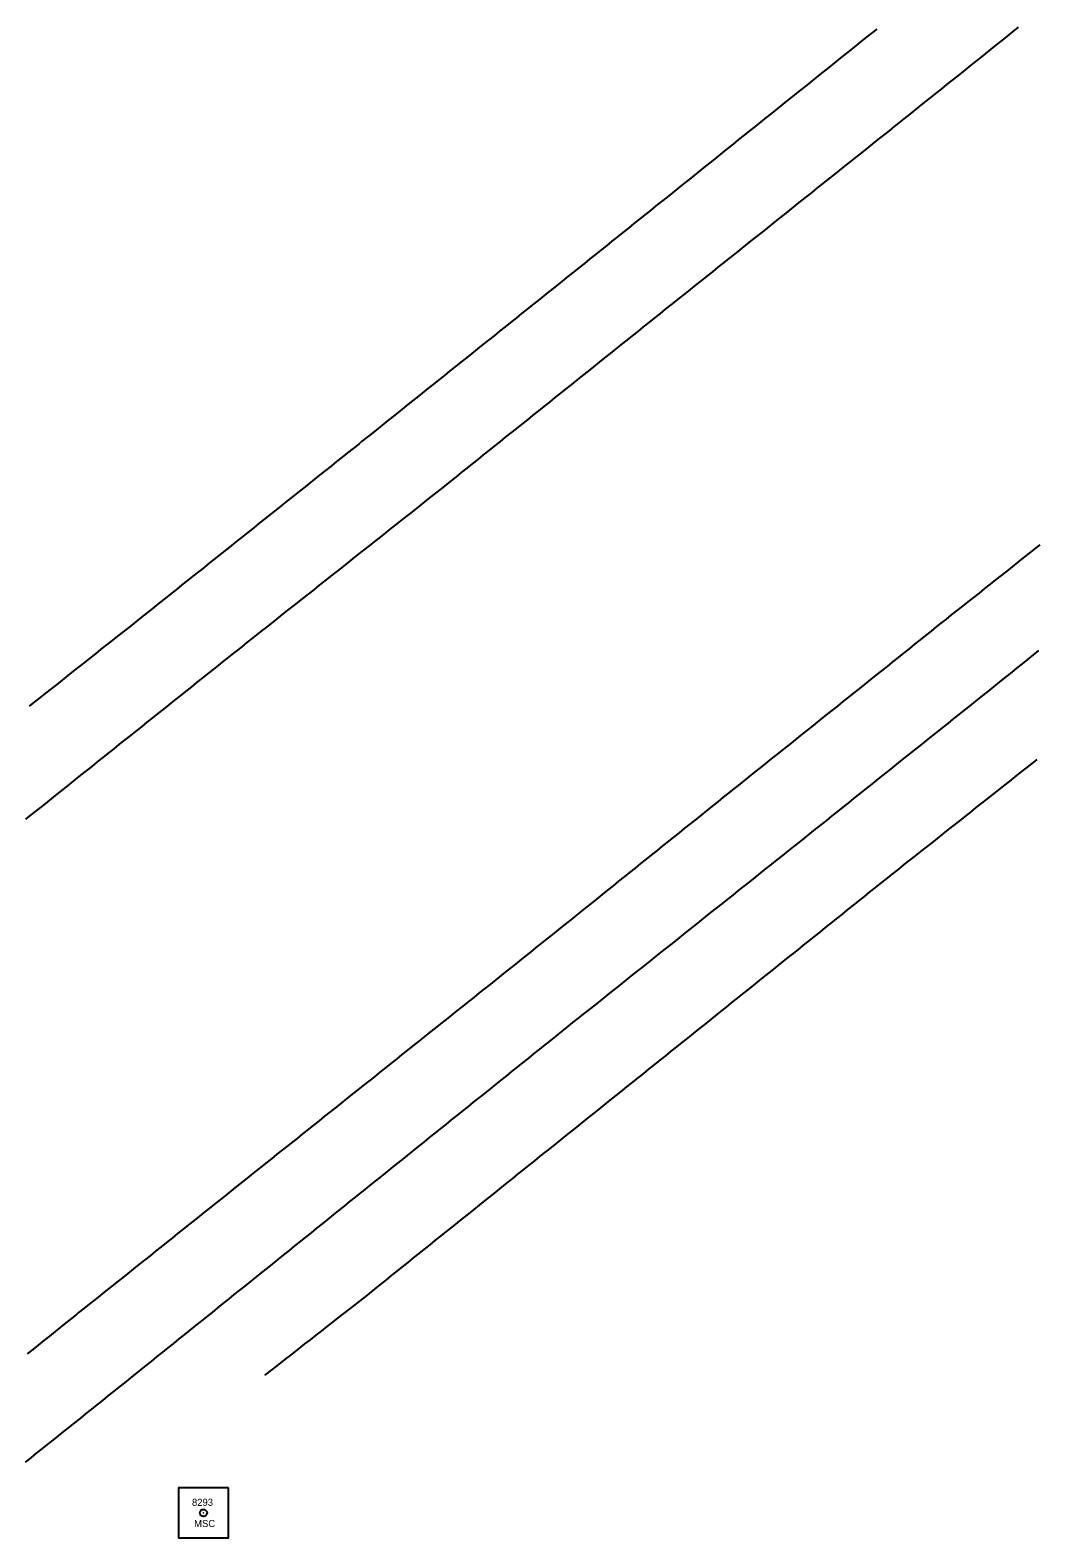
# Model space of a CAD drawing. Extents: x 205929 to 2357175, y -1785700 to 846739.
# Drawn here: x 2022372.4 to 2022514.8, y 806133.9 to 806347.3 of the extents above; entities that cross this region are included whole.
import ezdxf

# ---------------------------------------------------------------- set-up
doc = ezdxf.new("R2010")
doc.units = 0
for name, color, linetype in [('RD_HC_Survey', 7, 'Continuous'), ('RD_HC_txCode', 7, 'Continuous'), ('RD_Sketch1', 7, 'Continuous'), ('RD_SMD_Locator', 7, 'Continuous')]:
    doc.layers.add(name, color=color, linetype=linetype)

msp = doc.modelspace()

# ---------------------------------------------------------------- linework, layer by layer
at = {"layer": 'RD_HC_Survey'}
msp.add_lwpolyline([(2022400.46, 806140.98), (2022393.39, 806140.98), (2022393.39, 806133.91), (2022400.46, 806133.91)], close=True, dxfattribs=at)
msp.add_circle((2022396.93, 806137.44), 0.5, dxfattribs=at)
at = {"layer": 'RD_Sketch1'}
for points in [[(2022512.28, 806347.76), (2022511.5, 806347.14), (2022510.72, 806346.51), (2022509.94, 806345.89), (2022509.16, 806345.26), (2022508.38, 806344.64), (2022507.6, 806344.01), (2022506.82, 806343.39), (2022506.04, 806342.76), (2022505.26, 806342.14), (2022504.48, 806341.51), (2022503.7, 806340.89), (2022502.91, 806340.26), (2022502.13, 806339.64), (2022501.35, 806339.01), (2022500.57, 806338.39), (2022499.79, 806337.76), (2022499.01, 806337.14), (2022498.23, 806336.51), (2022497.45, 806335.89), (2022496.67, 806335.26), (2022495.89, 806334.64), (2022495.54, 806334.36), (2022494.76, 806333.73), (2022493.98, 806333.11), (2022493.2, 806332.49), (2022492.41, 806331.86), (2022491.63, 806331.24), (2022490.85, 806330.61), (2022490.07, 806329.99), (2022489.29, 806329.37), (2022488.51, 806328.74), (2022487.73, 806328.12), (2022486.94, 806327.49), (2022486.16, 806326.87), (2022486.16, 806326.87), (2022485.38, 806326.25), (2022484.6, 806325.62), (2022483.82, 806325), (2022483.04, 806324.37), (2022482.26, 806323.75), (2022481.47, 806323.13), (2022480.69, 806322.5), (2022479.91, 806321.88), (2022479.13, 806321.26), (2022478.35, 806320.63), (2022477.57, 806320.01), (2022476.79, 806319.38), (2022476, 806318.76), (2022475.22, 806318.14), (2022474.44, 806317.51), (2022473.66, 806316.89), (2022472.88, 806316.26), (2022472.1, 806315.64), (2022471.32, 806315.02), (2022470.53, 806314.39), (2022469.75, 806313.77), (2022468.97, 806313.14), (2022468.19, 806312.52), (2022467.41, 806311.9), (2022466.63, 806311.27), (2022465.85, 806310.65), (2022465.06, 806310.03), (2022464.28, 806309.4), (2022463.5, 806308.78), (2022463.08, 806308.44), (2022462.3, 806307.82), (2022461.52, 806307.19), (2022460.74, 806306.57), (2022459.96, 806305.94), (2022459.18, 806305.32), (2022458.4, 806304.69), (2022457.62, 806304.07), (2022456.84, 806303.44), (2022456.06, 806302.82), (2022455.28, 806302.19), (2022454.5, 806301.57), (2022453.72, 806300.94), (2022452.93, 806300.32), (2022452.15, 806299.69), (2022451.37, 806299.07), (2022450.59, 806298.44), (2022449.81, 806297.82), (2022449.03, 806297.19), (2022448.25, 806296.57), (2022447.47, 806295.94), (2022446.69, 806295.32), (2022445.91, 806294.69), (2022445.13, 806294.07), (2022444.35, 806293.44), (2022443.57, 806292.82), (2022442.79, 806292.19), (2022442.01, 806291.57), (2022441.22, 806290.95), (2022440.44, 806290.32), (2022439.66, 806289.7), (2022438.88, 806289.07), (2022438.1, 806288.45), (2022437.32, 806287.82), (2022436.54, 806287.2), (2022436.54, 806287.2), (2022435.76, 806286.57), (2022434.98, 806285.95), (2022434.2, 806285.32), (2022433.42, 806284.7), (2022432.64, 806284.07), (2022431.86, 806283.45), (2022431.34, 806283.03), (2022430.56, 806282.41), (2022429.77, 806281.79), (2022428.99, 806281.17), (2022428.21, 806280.55), (2022427.42, 806279.93), (2022426.64, 806279.31), (2022425.85, 806278.69), (2022425.07, 806278.07), (2022424.29, 806277.45), (2022423.5, 806276.82), (2022422.72, 806276.2), (2022421.93, 806275.58), (2022421.15, 806274.96), (2022420.37, 806274.34), (2022419.58, 806273.72), (2022418.8, 806273.1), (2022418.02, 806272.48), (2022417.23, 806271.86), (2022416.45, 806271.24), (2022415.66, 806270.62), (2022414.88, 806270), (2022414.1, 806269.37), (2022413.31, 806268.75), (2022412.53, 806268.13), (2022411.75, 806267.51), (2022410.96, 806266.89), (2022410.18, 806266.27), (2022409.39, 806265.65), (2022408.61, 806265.03), (2022407.83, 806264.41), (2022407.04, 806263.79), (2022406.26, 806263.17), (2022405.47, 806262.55), (2022404.69, 806261.93), (2022403.91, 806261.3), (2022403.12, 806260.68), (2022402.34, 806260.06), (2022401.56, 806259.44), (2022400.77, 806258.82), (2022400.64, 806258.72), (2022399.86, 806258.09), (2022399.08, 806257.47), (2022398.3, 806256.84), (2022397.51, 806256.22), (2022396.73, 806255.6), (2022395.95, 806254.97), (2022395.17, 806254.35), (2022394.39, 806253.72), (2022393.61, 806253.1), (2022392.83, 806252.48), (2022392.04, 806251.85), (2022391.26, 806251.23), (2022390.48, 806250.6), (2022389.7, 806249.98), (2022388.92, 806249.36), (2022388.14, 806248.73), (2022387.36, 806248.11), (2022387.36, 806248.11), (2022386.58, 806247.48), (2022385.79, 806246.86), (2022385.01, 806246.24), (2022384.23, 806245.61), (2022383.45, 806244.99), (2022382.67, 806244.36), (2022381.89, 806243.74), (2022381.11, 806243.12), (2022380.32, 806242.49), (2022379.54, 806241.87), (2022378.76, 806241.24), (2022377.98, 806240.62), (2022377.2, 806240), (2022376.42, 806239.37), (2022375.64, 806238.75), (2022374.85, 806238.12), (2022374.07, 806237.5), (2022373.29, 806236.88), (2022372.51, 806236.25), (2022371.73, 806235.63)], [(2022492.24, 806347.5), (2022491.45, 806346.87), (2022490.67, 806346.25), (2022489.89, 806345.62), (2022489.11, 806345), (2022488.33, 806344.37), (2022487.55, 806343.75), (2022486.77, 806343.12), (2022485.99, 806342.5), (2022485.21, 806341.87), (2022484.43, 806341.24), (2022483.65, 806340.62), (2022482.87, 806339.99), (2022482.09, 806339.37), (2022481.31, 806338.74), (2022480.53, 806338.12), (2022479.71, 806337.47), (2022478.93, 806336.84), (2022478.15, 806336.21), (2022477.37, 806335.59), (2022476.59, 806334.96), (2022475.81, 806334.34), (2022475.03, 806333.71), (2022474.25, 806333.09), (2022473.47, 806332.46), (2022472.69, 806331.84), (2022471.91, 806331.21), (2022471.13, 806330.58), (2022470.35, 806329.96), (2022469.57, 806329.33), (2022468.79, 806328.71), (2022468.01, 806328.08), (2022467.23, 806327.46), (2022467.23, 806327.46), (2022466.45, 806326.83), (2022465.67, 806326.21), (2022464.89, 806325.58), (2022464.11, 806324.95), (2022463.33, 806324.33), (2022462.55, 806323.7), (2022461.77, 806323.08), (2022460.99, 806322.45), (2022460.21, 806321.83), (2022459.43, 806321.2), (2022458.65, 806320.58), (2022457.87, 806319.95), (2022457.09, 806319.33), (2022456.31, 806318.7), (2022455.53, 806318.07), (2022454.75, 806317.45), (2022453.97, 806316.82), (2022453.19, 806316.2), (2022452.41, 806315.57), (2022451.63, 806314.95), (2022450.85, 806314.32), (2022450.07, 806313.7), (2022449.29, 806313.07), (2022449, 806312.83), (2022448.22, 806312.21), (2022447.43, 806311.58), (2022446.65, 806310.96), (2022445.87, 806310.33), (2022445.09, 806309.71), (2022444.31, 806309.09), (2022443.53, 806308.46), (2022442.75, 806307.84), (2022441.97, 806307.21), (2022441.19, 806306.59), (2022440.41, 806305.96), (2022439.63, 806305.34), (2022438.85, 806304.71), (2022438.06, 806304.09), (2022437.28, 806303.46), (2022436.5, 806302.84), (2022435.72, 806302.21), (2022434.94, 806301.59), (2022434.16, 806300.96), (2022433.38, 806300.34), (2022432.6, 806299.71), (2022431.82, 806299.09), (2022431.04, 806298.46), (2022430.26, 806297.84), (2022429.48, 806297.22), (2022428.69, 806296.59), (2022427.91, 806295.97), (2022427.13, 806295.34), (2022426.35, 806294.72), (2022425.57, 806294.09), (2022424.79, 806293.47), (2022424.01, 806292.84), (2022423.23, 806292.22), (2022422.45, 806291.59), (2022421.67, 806290.97), (2022420.89, 806290.34), (2022420.11, 806289.72), (2022419.32, 806289.09), (2022418.9, 806288.75), (2022418.11, 806288.13), (2022418.11, 806288.13), (2022417.33, 806287.5), (2022416.55, 806286.88), (2022415.77, 806286.26), (2022414.99, 806285.63), (2022414.21, 806285.01), (2022413.42, 806284.39), (2022412.64, 806283.76), (2022411.86, 806283.14), (2022411.08, 806282.52), (2022410.3, 806281.89), (2022409.52, 806281.27), (2022408.73, 806280.65), (2022407.95, 806280.02), (2022407.17, 806279.4), (2022406.39, 806278.77), (2022405.61, 806278.15), (2022404.83, 806277.53), (2022404.04, 806276.9), (2022403.26, 806276.28), (2022402.48, 806275.66), (2022401.7, 806275.03), (2022400.92, 806274.41), (2022400.13, 806273.79), (2022399.35, 806273.16), (2022398.57, 806272.54), (2022397.79, 806271.92), (2022397.01, 806271.29), (2022396.23, 806270.67), (2022395.44, 806270.05), (2022394.66, 806269.42), (2022393.88, 806268.8), (2022393.1, 806268.18), (2022392.32, 806267.55), (2022391.54, 806266.93), (2022390.75, 806266.3), (2022389.97, 806265.68), (2022389.19, 806265.06), (2022388.41, 806264.43), (2022387.63, 806263.81), (2022387.13, 806263.41), (2022386.34, 806262.79), (2022385.56, 806262.17), (2022384.78, 806261.55), (2022383.99, 806260.93), (2022383.21, 806260.31), (2022382.42, 806259.69), (2022381.64, 806259.07), (2022380.86, 806258.45), (2022380.07, 806257.83), (2022379.29, 806257.21), (2022378.5, 806256.59), (2022377.72, 806255.97), (2022376.94, 806255.34), (2022376.15, 806254.72), (2022375.37, 806254.1), (2022374.58, 806253.48), (2022373.8, 806252.86), (2022373.02, 806252.24), (2022372.23, 806251.62)], [(2022515.34, 806274.5), (2022514.55, 806273.87), (2022513.77, 806273.25), (2022512.99, 806272.63), (2022512.2, 806272.01), (2022511.42, 806271.39), (2022510.64, 806270.77), (2022509.85, 806270.15), (2022509.07, 806269.52), (2022508.29, 806268.9), (2022507.5, 806268.28), (2022506.72, 806267.66), (2022505.94, 806267.04), (2022505.15, 806266.42), (2022504.37, 806265.8), (2022503.59, 806265.17), (2022502.8, 806264.55), (2022502.02, 806263.93), (2022501.51, 806263.52), (2022500.72, 806262.9), (2022499.94, 806262.27), (2022499.16, 806261.65), (2022498.38, 806261.02), (2022497.6, 806260.4), (2022496.82, 806259.78), (2022496.04, 806259.15), (2022495.26, 806258.53), (2022494.48, 806257.9), (2022493.7, 806257.28), (2022492.91, 806256.65), (2022492.13, 806256.03), (2022491.35, 806255.41), (2022490.57, 806254.78), (2022489.79, 806254.16), (2022489.01, 806253.53), (2022488.23, 806252.91), (2022487.45, 806252.28), (2022486.67, 806251.66), (2022485.89, 806251.03), (2022485.1, 806250.41), (2022484.32, 806249.79), (2022483.54, 806249.16), (2022482.76, 806248.54), (2022481.98, 806247.91), (2022481.2, 806247.29), (2022480.42, 806246.66), (2022479.64, 806246.04), (2022478.86, 806245.42), (2022478.08, 806244.79), (2022477.29, 806244.17), (2022476.51, 806243.54), (2022476.51, 806243.54), (2022475.73, 806242.92), (2022474.95, 806242.29), (2022474.17, 806241.67), (2022473.39, 806241.04), (2022472.61, 806240.42), (2022472.07, 806239.99), (2022471.29, 806239.36), (2022470.51, 806238.74), (2022469.73, 806238.11), (2022468.95, 806237.49), (2022468.17, 806236.86), (2022467.39, 806236.23), (2022466.61, 806235.61), (2022465.83, 806234.98), (2022465.05, 806234.36), (2022464.27, 806233.73), (2022463.49, 806233.11), (2022462.71, 806232.48), (2022461.93, 806231.85), (2022461.15, 806231.23), (2022460.37, 806230.6), (2022459.59, 806229.98), (2022458.81, 806229.35), (2022458.03, 806228.72), (2022457.25, 806228.1), (2022456.47, 806227.47), (2022455.69, 806226.85), (2022454.91, 806226.22), (2022454.13, 806225.59), (2022453.35, 806224.97), (2022452.57, 806224.34), (2022451.8, 806223.72), (2022451.02, 806223.09), (2022450.24, 806222.47), (2022449.46, 806221.84), (2022448.68, 806221.21), (2022447.9, 806220.59), (2022447.12, 806219.96), (2022446.34, 806219.34), (2022445.56, 806218.71), (2022444.78, 806218.08), (2022444, 806217.46), (2022443.22, 806216.83), (2022442.44, 806216.21), (2022441.66, 806215.58), (2022440.88, 806214.95), (2022440.66, 806214.78), (2022439.88, 806214.16), (2022439.1, 806213.54), (2022438.32, 806212.91), (2022437.54, 806212.29), (2022436.75, 806211.66), (2022435.97, 806211.04), (2022435.19, 806210.42), (2022434.41, 806209.79), (2022433.63, 806209.17), (2022432.85, 806208.55), (2022432.06, 806207.92), (2022431.28, 806207.3), (2022430.5, 806206.68), (2022429.72, 806206.05), (2022428.94, 806205.43), (2022428.15, 806204.81), (2022427.37, 806204.18), (2022427.37, 806204.18), (2022426.59, 806203.56), (2022425.81, 806202.94), (2022425.03, 806202.31), (2022424.25, 806201.69), (2022423.46, 806201.06), (2022422.68, 806200.44), (2022421.9, 806199.82), (2022421.12, 806199.19), (2022420.34, 806198.57), (2022419.56, 806197.95), (2022418.77, 806197.32), (2022417.99, 806196.7), (2022417.21, 806196.08), (2022416.43, 806195.45), (2022415.65, 806194.83), (2022414.86, 806194.21), (2022414.08, 806193.58), (2022413.3, 806192.96), (2022412.52, 806192.33), (2022411.74, 806191.71), (2022410.96, 806191.09), (2022410.17, 806190.46), (2022409.39, 806189.84), (2022408.9, 806189.44), (2022408.11, 806188.82), (2022407.33, 806188.2), (2022406.55, 806187.57), (2022405.77, 806186.95), (2022404.99, 806186.32), (2022404.21, 806185.7), (2022403.42, 806185.08), (2022402.64, 806184.45), (2022401.86, 806183.83), (2022401.08, 806183.21), (2022400.3, 806182.58), (2022399.52, 806181.96), (2022398.74, 806181.33), (2022397.95, 806180.71), (2022397.17, 806180.09), (2022396.39, 806179.46), (2022395.61, 806178.84), (2022394.83, 806178.21), (2022394.05, 806177.59), (2022393.27, 806176.97), (2022392.48, 806176.34), (2022391.7, 806175.72), (2022390.92, 806175.09), (2022390.14, 806174.47), (2022389.36, 806173.85), (2022388.58, 806173.22), (2022387.79, 806172.6), (2022387.01, 806171.98), (2022386.23, 806171.35), (2022385.45, 806170.73), (2022384.67, 806170.1), (2022383.89, 806169.48), (2022383.11, 806168.86), (2022382.32, 806168.23), (2022381.54, 806167.61), (2022380.76, 806166.98), (2022379.98, 806166.36), (2022379.2, 806165.74), (2022379.01, 806165.58), (2022378.23, 806164.96), (2022377.45, 806164.33), (2022376.67, 806163.71), (2022375.89, 806163.08), (2022375.11, 806162.45), (2022374.33, 806161.83), (2022373.55, 806161.2), (2022372.77, 806160.57), (2022371.99, 806159.95)], [(2022515.16, 806259.53), (2022514.38, 806258.9), (2022513.6, 806258.27), (2022512.83, 806257.65), (2022512.05, 806257.02), (2022511.66, 806256.71), (2022510.88, 806256.08), (2022510.1, 806255.46), (2022509.32, 806254.83), (2022508.54, 806254.21), (2022507.76, 806253.58), (2022506.98, 806252.96), (2022506.2, 806252.34), (2022505.41, 806251.71), (2022504.63, 806251.09), (2022503.85, 806250.46), (2022503.07, 806249.84), (2022502.29, 806249.21), (2022501.51, 806248.59), (2022500.73, 806247.97), (2022499.95, 806247.34), (2022499.17, 806246.72), (2022498.38, 806246.09), (2022497.6, 806245.47), (2022496.82, 806244.84), (2022496.04, 806244.22), (2022495.26, 806243.6), (2022494.48, 806242.97), (2022493.7, 806242.35), (2022492.92, 806241.72), (2022492.14, 806241.1), (2022491.35, 806240.47), (2022490.57, 806239.85), (2022489.79, 806239.23), (2022489.01, 806238.6), (2022489.01, 806238.6), (2022488.23, 806237.98), (2022487.45, 806237.35), (2022486.67, 806236.73), (2022485.89, 806236.1), (2022485.11, 806235.48), (2022484.33, 806234.86), (2022483.54, 806234.23), (2022482.76, 806233.61), (2022481.98, 806232.98), (2022481.2, 806232.36), (2022480.42, 806231.73), (2022479.68, 806231.14), (2022478.9, 806230.52), (2022478.12, 806229.9), (2022477.34, 806229.27), (2022476.55, 806228.65), (2022475.77, 806228.03), (2022474.99, 806227.4), (2022474.21, 806226.78), (2022472.64, 806225.54), (2022471.86, 806224.91), (2022471.08, 806224.29), (2022470.3, 806223.67), (2022469.52, 806223.04), (2022468.73, 806222.42), (2022467.95, 806221.8), (2022467.17, 806221.17), (2022466.39, 806220.55), (2022465.61, 806219.93), (2022464.82, 806219.3), (2022464.04, 806218.68), (2022463.26, 806218.06), (2022462.48, 806217.43), (2022461.69, 806216.81), (2022460.91, 806216.19), (2022460.13, 806215.56), (2022459.35, 806214.94), (2022458.57, 806214.32), (2022457.78, 806213.69), (2022457, 806213.07), (2022456.22, 806212.45), (2022455.44, 806211.82), (2022454.66, 806211.2), (2022453.87, 806210.58), (2022453.09, 806209.95), (2022452.31, 806209.33), (2022451.53, 806208.71), (2022450.75, 806208.09), (2022449.96, 806207.46), (2022449.18, 806206.84), (2022448.39, 806206.21), (2022447.61, 806205.58), (2022446.83, 806204.95), (2022446.05, 806204.33), (2022445.27, 806203.7), (2022444.49, 806203.08), (2022443.71, 806202.45), (2022442.93, 806201.82), (2022442.15, 806201.2), (2022441.37, 806200.57), (2022440.59, 806199.95), (2022439.81, 806199.32), (2022439.03, 806198.69), (2022438.25, 806198.07), (2022438.25, 806198.07), (2022437.47, 806197.44), (2022436.69, 806196.82), (2022435.91, 806196.19), (2022435.13, 806195.57), (2022434.35, 806194.94), (2022433.57, 806194.31), (2022432.79, 806193.69), (2022432.01, 806193.06), (2022431.23, 806192.44), (2022430.45, 806191.81), (2022429.67, 806191.18), (2022428.89, 806190.56), (2022428.11, 806189.93), (2022427.33, 806189.31), (2022426.56, 806188.68), (2022425.78, 806188.05), (2022425, 806187.43), (2022424.22, 806186.8), (2022423.44, 806186.18), (2022422.66, 806185.55), (2022421.88, 806184.92), (2022421.1, 806184.3), (2022420.32, 806183.67), (2022419.54, 806183.05), (2022419.17, 806182.75), (2022418.39, 806182.13), (2022417.61, 806181.5), (2022416.83, 806180.87), (2022416.05, 806180.25), (2022415.28, 806179.62), (2022414.5, 806178.99), (2022413.72, 806178.36), (2022413.72, 806178.36), (2022412.94, 806177.74), (2022412.16, 806177.11), (2022411.38, 806176.48), (2022410.6, 806175.86), (2022409.82, 806175.23), (2022409.04, 806174.6), (2022408.26, 806173.98), (2022407.48, 806173.35), (2022406.71, 806172.72), (2022405.93, 806172.1), (2022405.15, 806171.47), (2022404.37, 806170.84), (2022403.59, 806170.22), (2022402.81, 806169.59), (2022402.03, 806168.96), (2022401.25, 806168.34), (2022400.47, 806167.71), (2022399.69, 806167.08), (2022398.91, 806166.45), (2022398.14, 806165.83), (2022397.36, 806165.2), (2022396.58, 806164.57), (2022395.8, 806163.95), (2022395.02, 806163.32), (2022394.24, 806162.69), (2022393.46, 806162.07), (2022392.68, 806161.44), (2022391.9, 806160.81), (2022391.12, 806160.19), (2022390.34, 806159.56), (2022389.57, 806158.93), (2022388.79, 806158.31), (2022388.01, 806157.68), (2022387.31, 806157.12), (2022386.53, 806156.5), (2022385.75, 806155.87), (2022384.97, 806155.25), (2022384.19, 806154.62), (2022383.41, 806154), (2022382.63, 806153.37), (2022381.85, 806152.75), (2022381.07, 806152.12), (2022380.29, 806151.5), (2022379.51, 806150.87), (2022378.73, 806150.25), (2022377.95, 806149.62), (2022377.16, 806149), (2022376.38, 806148.37), (2022375.6, 806147.75), (2022374.82, 806147.12), (2022374.04, 806146.5), (2022373.26, 806145.88), (2022372.48, 806145.25), (2022371.7, 806144.63)], [(2022514.92, 806244.1), (2022514.13, 806243.48), (2022513.35, 806242.86), (2022512.56, 806242.24), (2022511.78, 806241.62), (2022510.99, 806241), (2022510.21, 806240.38), (2022509.43, 806239.76), (2022508.64, 806239.14), (2022508.64, 806239.14), (2022507.86, 806238.52), (2022507.07, 806237.9), (2022506.29, 806237.28), (2022505.51, 806236.66), (2022504.72, 806236.04), (2022503.94, 806235.42), (2022503.15, 806234.8), (2022502.37, 806234.17), (2022501.59, 806233.55), (2022500.8, 806232.93), (2022500.02, 806232.31), (2022499.23, 806231.69), (2022498.45, 806231.07), (2022497.66, 806230.45), (2022496.88, 806229.83), (2022496.1, 806229.21), (2022495.31, 806228.59), (2022494.53, 806227.97), (2022494.31, 806227.8), (2022493.53, 806227.17), (2022492.75, 806226.55), (2022491.97, 806225.92), (2022491.19, 806225.3), (2022490.41, 806224.67), (2022489.63, 806224.05), (2022488.85, 806223.42), (2022488.07, 806222.8), (2022487.29, 806222.17), (2022486.51, 806221.55), (2022485.73, 806220.92), (2022484.95, 806220.3), (2022484.17, 806219.67), (2022483.39, 806219.04), (2022482.61, 806218.42), (2022481.83, 806217.79), (2022481.05, 806217.17), (2022480.27, 806216.54), (2022479.49, 806215.92), (2022478.71, 806215.29), (2022477.93, 806214.67), (2022477.15, 806214.04), (2022476.37, 806213.42), (2022475.59, 806212.79), (2022474.81, 806212.17), (2022474.03, 806211.54), (2022473.25, 806210.92), (2022472.47, 806210.29), (2022471.69, 806209.67), (2022470.91, 806209.04), (2022470.13, 806208.41), (2022469.35, 806207.79), (2022468.57, 806207.16), (2022467.79, 806206.54), (2022467.01, 806205.91), (2022466.23, 806205.29), (2022465.45, 806204.66), (2022464.67, 806204.04), (2022463.89, 806203.41), (2022463.11, 806202.79), (2022462.33, 806202.16), (2022461.55, 806201.54), (2022460.77, 806200.91), (2022459.99, 806200.29), (2022459.21, 806199.66), (2022459.21, 806199.66), (2022458.43, 806199.03), (2022457.65, 806198.41), (2022456.87, 806197.78), (2022456.27, 806197.3), (2022455.49, 806196.68), (2022454.71, 806196.05), (2022453.93, 806195.43), (2022453.15, 806194.8), (2022452.37, 806194.17), (2022451.59, 806193.55), (2022450.81, 806192.92), (2022450.03, 806192.3), (2022449.25, 806191.67), (2022448.47, 806191.05), (2022447.69, 806190.42), (2022446.91, 806189.8), (2022446.13, 806189.17), (2022445.35, 806188.54), (2022444.57, 806187.92), (2022443.79, 806187.29), (2022443.01, 806186.67), (2022442.23, 806186.04), (2022441.45, 806185.42), (2022440.67, 806184.79), (2022439.89, 806184.17), (2022439.11, 806183.54), (2022438.33, 806182.91), (2022437.55, 806182.29), (2022436.77, 806181.66), (2022435.99, 806181.04), (2022435.21, 806180.41), (2022434.43, 806179.79), (2022433.65, 806179.16), (2022432.87, 806178.53), (2022432.87, 806178.53), (2022432.09, 806177.91), (2022431.31, 806177.28), (2022430.53, 806176.66), (2022429.75, 806176.03), (2022428.97, 806175.41), (2022428.19, 806174.78), (2022427.41, 806174.16), (2022426.63, 806173.53), (2022425.85, 806172.9), (2022425.07, 806172.28), (2022424.29, 806171.65), (2022423.51, 806171.03), (2022422.73, 806170.4), (2022421.95, 806169.78), (2022421.17, 806169.15), (2022420.39, 806168.52), (2022419.61, 806167.9), (2022418.83, 806167.27), (2022418.34, 806166.88), (2022417.55, 806166.27), (2022416.76, 806165.65), (2022415.97, 806165.04), (2022415.18, 806164.42), (2022414.4, 806163.81), (2022413.61, 806163.19), (2022412.82, 806162.58), (2022412.03, 806161.96), (2022411.24, 806161.35), (2022410.45, 806160.73), (2022409.67, 806160.12), (2022408.88, 806159.5), (2022408.09, 806158.89), (2022407.3, 806158.27), (2022406.51, 806157.66), (2022405.72, 806157.04), (2022405.56, 806156.92)]]:
    msp.add_lwpolyline(points, dxfattribs=at)
at = {"layer": 'RD_SMD_Locator'}
msp.add_circle((2022396.93, 806137.44), 0.001, dxfattribs=at)

# ---------------------------------------------------------------- texts
at = {"layer": 'RD_HC_txCode'}
for s, p in [('8293', (2022395.3, 806138.44)), ('MSC', (2022395.61, 806135.44))]:
    msp.add_text(s, height=1, dxfattribs=at).set_placement(p)

doc.saveas('drawing.dxf')
